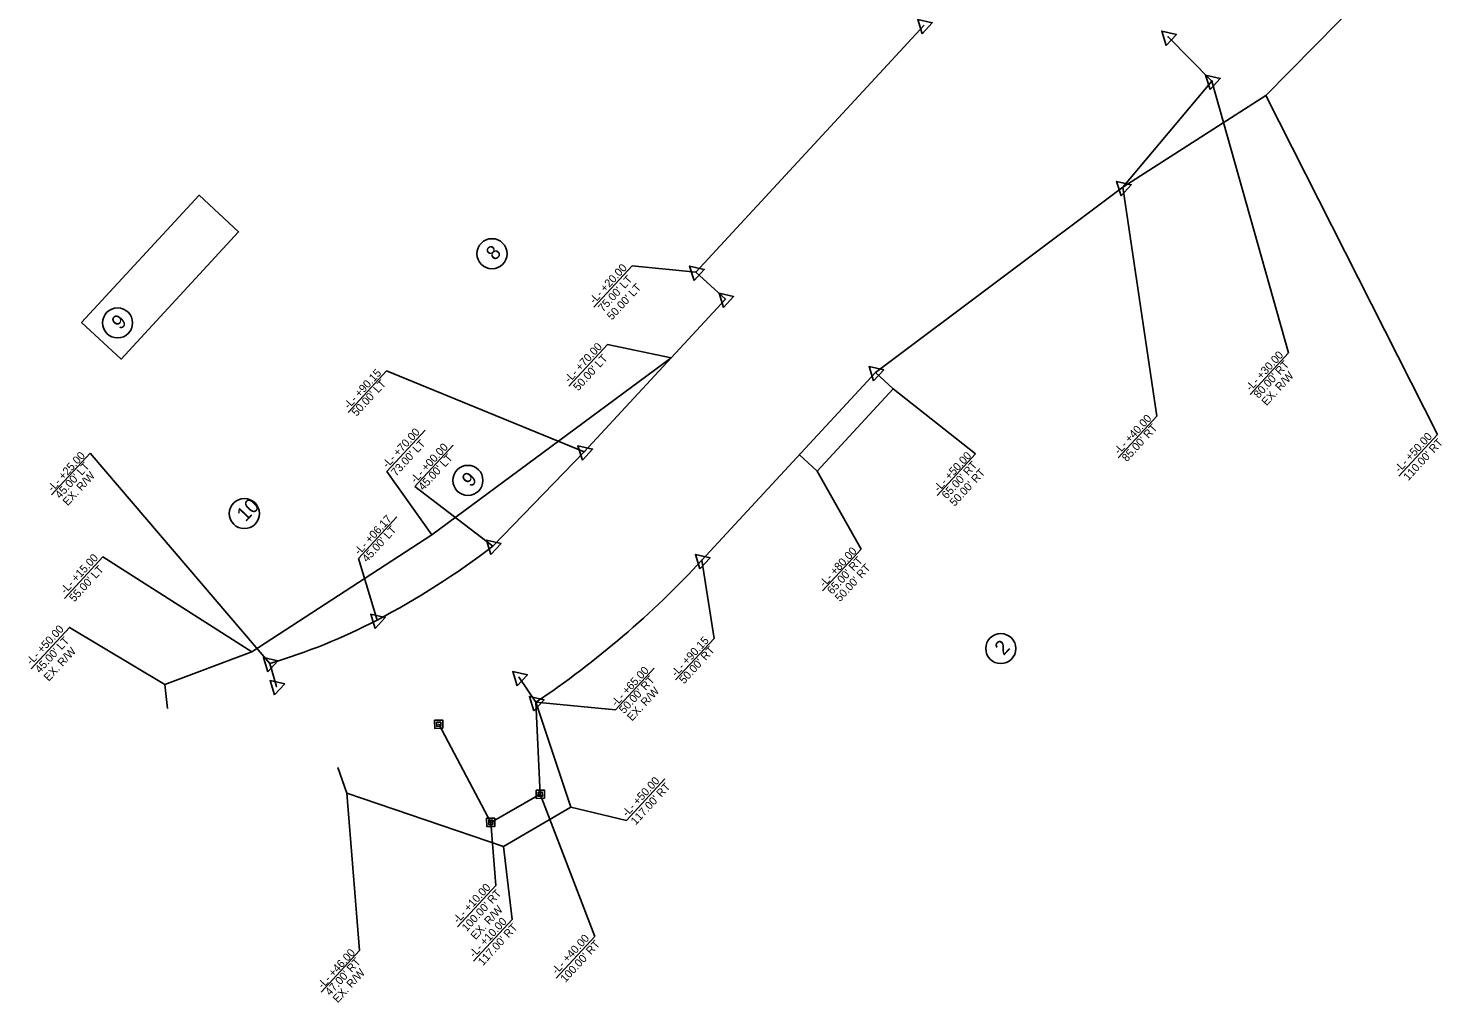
# Model space of a CAD drawing. Extents: x 1768436 to 1770837, y 999770 to 1004574.
# Drawn here: x 1768436 to 1769320, y 999770 to 1000379 of the extents above; entities that cross this region are included whole.
import ezdxf

# ---------------------------------------------------------------- set-up
doc = ezdxf.new("R2010")
doc.units = 0
for name, color, linetype in [('Coir Fiber Wattle with PAM CG CELL', 7, 'Continuous'), ('Label A CG CELL', 7, 'Continuous'), ('Label C Final CELL', 7, 'Continuous'), ('Rock Inlet Sediment Trap Type B CG CELL', 7, 'Continuous'), ('Rock Inlet Sediment Trap Type C CG CELL', 7, 'Continuous'), ('Rock Pipe Inlet Sediment Trap Type A CG CELL', 7, 'Continuous'), ('Rock Pipe Inlet Sediment Trap Type B CG CELL', 7, 'Continuous'), ('Rock Silt Check Type A CG CELL', 7, 'Continuous'), ('Scratch_Level_5', 7, 'Continuous')]:
    doc.layers.add(name, color=color, linetype=linetype)

msp = doc.modelspace()

# ---------------------------------------------------------------- linework, layer by layer
at = {"layer": 'Label A CG CELL'}
msp.add_lwpolyline([(1768469.46, 1000195.01), (1768542.95, 1000274.52), (1768567.7, 1000251.64), (1768494.21, 1000172.13)], close=True, dxfattribs=at)
for centre in [(1768726.04, 1000238.01), (1768492.03, 1000194.77), (1768710.96, 1000096.32), (1768571.27, 1000075.59), (1769043.99, 999991.22)]:
    msp.add_circle(centre, 9.41, dxfattribs=at)
at = {"layer": 'Label C Final CELL'}
for p, q in [((1768790.23, 999811.23), (1768756.23, 999900.16)), ((1768728.47, 999843.17), (1768725.26, 999882.59)), ((1768704.44, 999817.18), (1768728.47, 999843.17)), ((1768766.2, 999785.24), (1768790.23, 999811.23))]:
    msp.add_line(p, q, dxfattribs=at)
at = {"layer": 'Rock Inlet Sediment Trap Type B CG CELL'}
for p, q in [((1768756.23, 999900.16), (1768753.4, 999957.63)), ((1768725.26, 999882.59), (1768692.72, 999943.89)), ((1768725.26, 999882.59), (1768756.23, 999900.16))]:
    msp.add_line(p, q, dxfattribs=at)
at = {"layer": 'Rock Inlet Sediment Trap Type C CG CELL'}
for p, q in [((1769223.88, 1000176.08), (1769175.95, 1000345.93)), ((1769141.43, 1000136.4), (1769120.32, 1000279.54)), ((1768789.59, 1000204.54), (1768813.61, 1000230.53)), ((1768813.61, 1000230.53), (1768853.49, 1000226.59)), ((1769199.85, 1000150.08), (1769223.88, 1000176.08)), ((1768636.1, 1000138.81), (1768660.13, 1000164.81)), ((1768660.13, 1000164.81), (1768783.71, 1000114.27)), ((1769117.41, 1000110.4), (1769141.43, 1000136.4)), ((1768450.83, 1000087.26), (1768474.86, 1000113.26)), ((1768474.86, 1000113.26), (1768587.09, 999981.92)), ((1768677.79, 1000092.44), (1768701.82, 1000118.44)), ((1768677.79, 1000092.44), (1768726.51, 1000055.24)), ((1768642.6, 1000047.55), (1768666.63, 1000073.54)), ((1768642.6, 1000047.55), (1768654.18, 1000009.04)), ((1768864.77, 999997.58), (1768857.15, 1000046.39)), ((1768840.74, 999971.58), (1768864.77, 999997.58)), ((1768803.26, 999952.9), (1768827.29, 999978.9)), ((1768803.26, 999952.9), (1768753.4, 999957.63))]:
    msp.add_line(p, q, dxfattribs=at)
at = {"layer": 'Rock Pipe Inlet Sediment Trap Type A CG CELL'}
for p, q in [((1769148.58, 1000373.53), (1769148.58, 1000373.53)), ((1769175.94, 1000345.94), (1769175.94, 1000345.94)), ((1769120.31, 1000279.55), (1769120.31, 1000279.55)), ((1768853.49, 1000226.59), (1768853.49, 1000226.59)), ((1768871.85, 1000209.63), (1768871.85, 1000209.63)), ((1768965.64, 1000163.79), (1768965.64, 1000163.79)), ((1768783.71, 1000114.27), (1768783.71, 1000114.27)), ((1768726.51, 1000055.24), (1768726.51, 1000055.24)), ((1768857.15, 1000046.39), (1768857.15, 1000046.39)), ((1768654.18, 1000009.04), (1768654.18, 1000009.04)), ((1768587.09, 999981.92), (1768587.09, 999981.92)), ((1768742.96, 999973.19), (1768742.96, 999973.19)), ((1768591.34, 999967.53), (1768591.34, 999967.53)), ((1768753.4, 999957.63), (1768753.4, 999957.63)), ((1768692.72, 999943.89), (1768692.72, 999943.89)), ((1768756.23, 999900.16), (1768756.23, 999900.16)), ((1768725.26, 999882.59), (1768725.26, 999882.59))]:
    msp.add_line(p, q, dxfattribs=at)
for points in [[(1768994.84, 1000375.53), (1768992.08, 1000384.47), (1769001.2, 1000382.41)], [(1769147.38, 1000368.26), (1769144.62, 1000377.2), (1769153.74, 1000375.14)], [(1769174.74, 1000340.67), (1769171.98, 1000349.61), (1769181.1, 1000347.55)], [(1769119.11, 1000274.28), (1769116.35, 1000283.22), (1769125.47, 1000281.16)], [(1768852.29, 1000221.32), (1768849.53, 1000230.26), (1768858.66, 1000228.2)], [(1768870.65, 1000204.35), (1768867.89, 1000213.29), (1768877.01, 1000211.23)], [(1768964.44, 1000158.51), (1768961.68, 1000167.45), (1768970.8, 1000165.39)], [(1768782.51, 1000109), (1768779.75, 1000117.94), (1768788.88, 1000115.88)], [(1768725.31, 1000049.97), (1768722.54, 1000058.91), (1768731.67, 1000056.85)], [(1768855.95, 1000041.12), (1768853.19, 1000050.06), (1768862.31, 1000048)], [(1768652.98, 1000003.76), (1768650.22, 1000012.7), (1768659.34, 1000010.64)], [(1768585.89, 999976.64), (1768583.13, 999985.58), (1768592.26, 999983.52)], [(1768590.15, 999962.26), (1768587.38, 999971.2), (1768596.51, 999969.14)], [(1768741.76, 999967.92), (1768739, 999976.86), (1768748.13, 999974.8)], [(1768752.2, 999952.36), (1768749.44, 999961.29), (1768758.56, 999959.24)], [(1768690.14, 999946.4), (1768695.23, 999946.48), (1768695.3, 999941.39), (1768690.21, 999941.31)], [(1768691.43, 999945.15), (1768693.98, 999945.18), (1768694.01, 999942.64), (1768691.47, 999942.6)], [(1768753.65, 999902.67), (1768758.74, 999902.74), (1768758.81, 999897.65), (1768753.72, 999897.58)], [(1768754.94, 999901.41), (1768757.48, 999901.45), (1768757.52, 999898.9), (1768754.97, 999898.87)], [(1768722.68, 999885.1), (1768727.77, 999885.17), (1768727.84, 999880.08), (1768722.75, 999880.01)], [(1768723.97, 999883.85), (1768726.51, 999883.88), (1768726.55, 999881.34), (1768724.01, 999881.3)]]:
    msp.add_lwpolyline(points, close=True, dxfattribs=at)
for centre, radius in [((1769148.58, 1000373.53), 0.112), ((1769175.94, 1000345.94), 0.112), ((1769120.31, 1000279.55), 0.112), ((1768853.49, 1000226.59), 0.112), ((1768871.85, 1000209.63), 0.112), ((1768965.64, 1000163.79), 0.112), ((1768783.71, 1000114.27), 0.112), ((1768726.51, 1000055.24), 0.112), ((1768857.15, 1000046.39), 0.112), ((1768654.18, 1000009.04), 0.112), ((1768587.09, 999981.92), 0.112), ((1768742.96, 999973.19), 0.112), ((1768591.34, 999967.53), 0.112), ((1768753.4, 999957.63), 0.112), ((1768692.72, 999943.89), 0.06), ((1768756.23, 999900.16), 0.06), ((1768725.26, 999882.59), 0.06)]:
    msp.add_circle(centre, radius, dxfattribs=at)
at = {"layer": 'Rock Pipe Inlet Sediment Trap Type B CG CELL'}
for p, q in [((1769316.86, 1000125.05), (1769209.7, 1000336.88)), ((1768774.09, 1000155.19), (1768798.12, 1000181.18)), ((1768798.12, 1000181.18), (1768837.91, 1000172.91)), ((1769028.28, 1000112.97), (1768976.67, 1000153.59)), ((1768660.24, 1000101.82), (1768684.27, 1000127.82)), ((1769292.83, 1000099.05), (1769316.86, 1000125.05)), ((1769004.25, 1000086.97), (1769028.28, 1000112.97)), ((1768660.24, 1000101.82), (1768688.46, 1000062.21)), ((1768956.67, 1000053.35), (1768929.15, 1000102.19)), ((1768932.64, 1000027.36), (1768956.67, 1000053.35)), ((1768810.02, 999883.84), (1768834.05, 999909.84)), ((1768810.02, 999883.84), (1768775.39, 999892.02)), ((1768738.57, 999821.89), (1768733.23, 999867.58)), ((1768714.54, 999795.89), (1768738.57, 999821.89))]:
    msp.add_line(p, q, dxfattribs=at)
for points in [[(1768458.78, 1000022.47), (1768482.81, 1000048.47), (1768575.89, 999989.14)], [(1768437.94, 999978.46), (1768461.97, 1000004.46), (1768521.53, 999968.74)], [(1768619.18, 999776.49), (1768643.21, 999802.49), (1768635.4, 999900.87)]]:
    msp.add_lwpolyline(points, dxfattribs=at)
at = {"layer": 'Rock Silt Check Type A CG CELL'}
for p, q in [((1768853.49, 1000226.59), (1768996.04, 1000380.8)), ((1769175.95, 1000345.93), (1769148.59, 1000373.52)), ((1769120.32, 1000279.54), (1769175.95, 1000345.93)), ((1768965.65, 1000163.78), (1769120.32, 1000279.54)), ((1768853.49, 1000226.59), (1768871.85, 1000209.62)), ((1768783.71, 1000114.27), (1768871.85, 1000209.62)), ((1768857.15, 1000046.39), (1768965.65, 1000163.78)), ((1768726.51, 1000055.24), (1768783.71, 1000114.27)), ((1768587.09, 999981.92), (1768591.34, 999967.53)), ((1768753.4, 999957.63), (1768742.96, 999973.19))]:
    msp.add_line(p, q, dxfattribs=at)
for centre, radius, start, end in [((1768427.56, 1000443.48), 490, 297.54772, 307.59628), ((1768427.56, 1000443.48), 585, 303.84796, 317.25123), ((1768480.75, 1000341.52), 375, 286.47443, 297.54772)]:
    msp.add_arc(centre, radius, start, end, dxfattribs=at)
at = {"layer": 'Scratch_Level_5'}
for p, q in [((1769209.7, 1000336.88), (1769281.34, 1000409.81)), ((1769120.32, 1000279.54), (1769209.7, 1000336.88)), ((1768688.46, 1000062.21), (1768837.91, 1000172.91)), ((1768976.66, 1000153.59), (1768965.65, 1000163.78)), ((1768929.15, 1000102.19), (1768976.66, 1000153.59)), ((1768929.15, 1000102.19), (1768918.13, 1000112.37)), ((1768575.89, 999989.14), (1768688.46, 1000062.21)), ((1768521.53, 999968.74), (1768575.89, 999989.14)), ((1768521.53, 999968.74), (1768523.16, 999953.83)), ((1768775.39, 999892.02), (1768753.4, 999957.63)), ((1768635.4, 999900.87), (1768629.77, 999916.91)), ((1768635.4, 999900.87), (1768733.23, 999867.58)), ((1768733.23, 999867.58), (1768775.39, 999892.02))]:
    msp.add_line(p, q, dxfattribs=at)

# ---------------------------------------------------------------- texts
at = {"layer": 'Coir Fiber Wattle with PAM CG CELL'}
for s, p in [('8', (1768727.81, 1000233.27)), ('9', (1768493.8, 1000190.03)), ('9', (1768712.73, 1000091.59)), ('10', (1768572.07, 1000070.03)), ('2', (1769045.76, 999986.48))]:
    msp.add_text(s, height=9, rotation=46.64664, dxfattribs=at).set_placement(p)
at = {"layer": 'Label C Final CELL'}
for s, p in [('-L- +10.00', (1768704.73, 999819.06)), ("100.00' RT", (1768710.24, 999813.97)), ('EX. R/W', (1768715.75, 999808.88)), ('-L- +40.00', (1768766.37, 999787.23)), ("100.00' RT", (1768771.87, 999782.14))]:
    msp.add_text(s, height=5, rotation=47.25123, dxfattribs=at).set_placement(p)
at = {"layer": 'Rock Inlet Sediment Trap Type C CG CELL'}
for s, p in [('-L- +20.00', (1768789.93, 1000206.37)), ("75.00' LT", (1768795.44, 1000201.28)), ("50.00' LT", (1768800.94, 1000196.19)), ('-L- +30.00', (1769200.12, 1000151.83)), ('-L- +90.15', (1768636.48, 1000140.62)), ("80.00' RT", (1769205.08, 1000147.24)), ('EX. R/W', (1769210.04, 1000142.66)), ("50.00' LT", (1768641.43, 1000136.03)), ('-L- +40.00', (1769117.79, 1000112.2)), ("85.00' RT", (1769122.74, 1000107.62)), ('-L- +25.00', (1768451.34, 1000088.94)), ('-L- +00.00', (1768678.17, 1000094.25)), ("45.00' LT", (1768683.13, 1000089.66)), ("45.00' LT", (1768456.11, 1000084.53)), ('EX. R/W', (1768460.89, 1000080.11)), ('-L- +06.17', (1768642.98, 1000049.35)), ("45.00' LT", (1768647.93, 1000044.77)), ('-L- +90.15', (1768841.12, 999973.38)), ("50.00' RT", (1768846.08, 999968.8)), ('-L- +65.00', (1768803.62, 999954.72)), ("50.00' RT", (1768808.58, 999950.14)), ('EX. R/W', (1768813.54, 999945.56))]:
    msp.add_text(s, height=5, rotation=47.25123, dxfattribs=at).set_placement(p)
at = {"layer": 'Rock Pipe Inlet Sediment Trap Type B CG CELL'}
for s, p in [('-L- +70.00', (1768774.41, 1000157.05)), ("50.00' LT", (1768779.92, 1000151.96)), ('-L- +70.00', (1768660.56, 1000103.68)), ("73.00' LT", (1768666.06, 1000098.59)), ('-L- +50.00', (1769293.15, 1000100.91)), ("110.00' RT", (1769298.65, 1000095.82)), ('-L- +50.00', (1769005.21, 1000088.91)), ("65.00' RT", (1769010.17, 1000084.33)), ("50.00' RT", (1769015.12, 1000079.75)), ('-L- +15.00', (1768459.49, 1000025.09)), ('-L- +80.00', (1768933.6, 1000029.3)), ("55.00' LT", (1768464.99, 1000020)), ("65.00' RT", (1768938.56, 1000024.72)), ("50.00' RT", (1768943.51, 1000020.14)), ('-L- +50.00', (1768438.02, 999980.54)), ("45.00' LT", (1768443.53, 999975.45)), ('EX. R/W', (1768449.04, 999970.36)), ('-L- +50.00', (1768810.33, 999885.7)), ("117.00' RT", (1768815.84, 999880.61)), ('-L- +10.00', (1768714.86, 999797.75)), ("117.00' RT", (1768720.37, 999792.66)), ('-L- +46.00', (1768620.1, 999778.25)), ("47.00' RT", (1768624.87, 999773.84)), ('EX. R/W', (1768629.64, 999769.43))]:
    msp.add_text(s, height=5, rotation=47.25123, dxfattribs=at).set_placement(p)

doc.saveas('drawing.dxf')
